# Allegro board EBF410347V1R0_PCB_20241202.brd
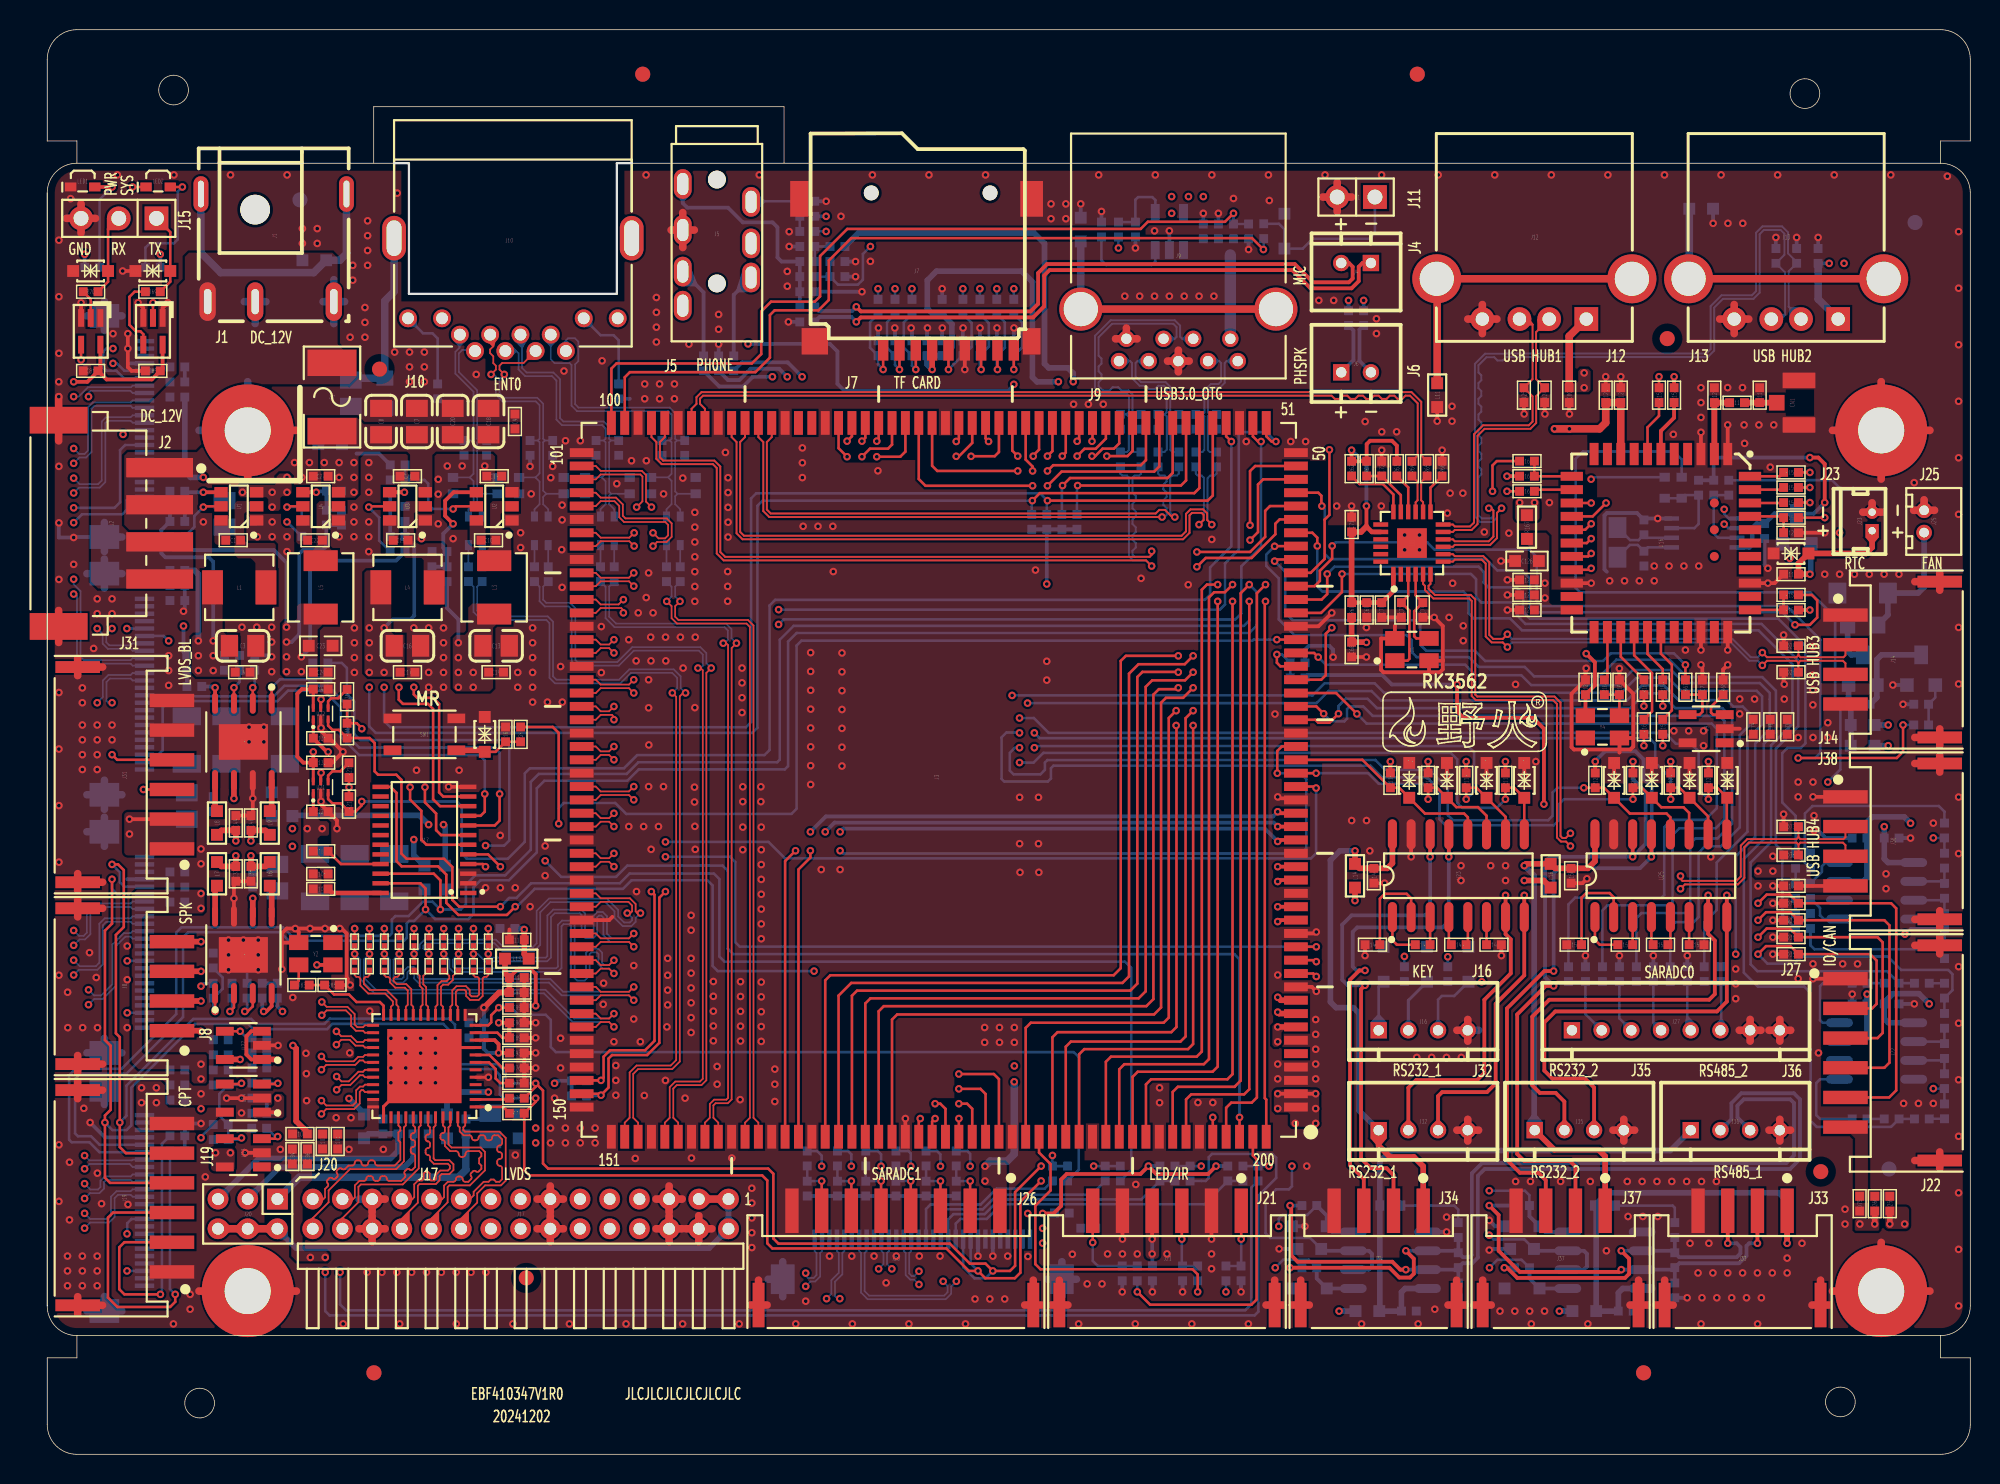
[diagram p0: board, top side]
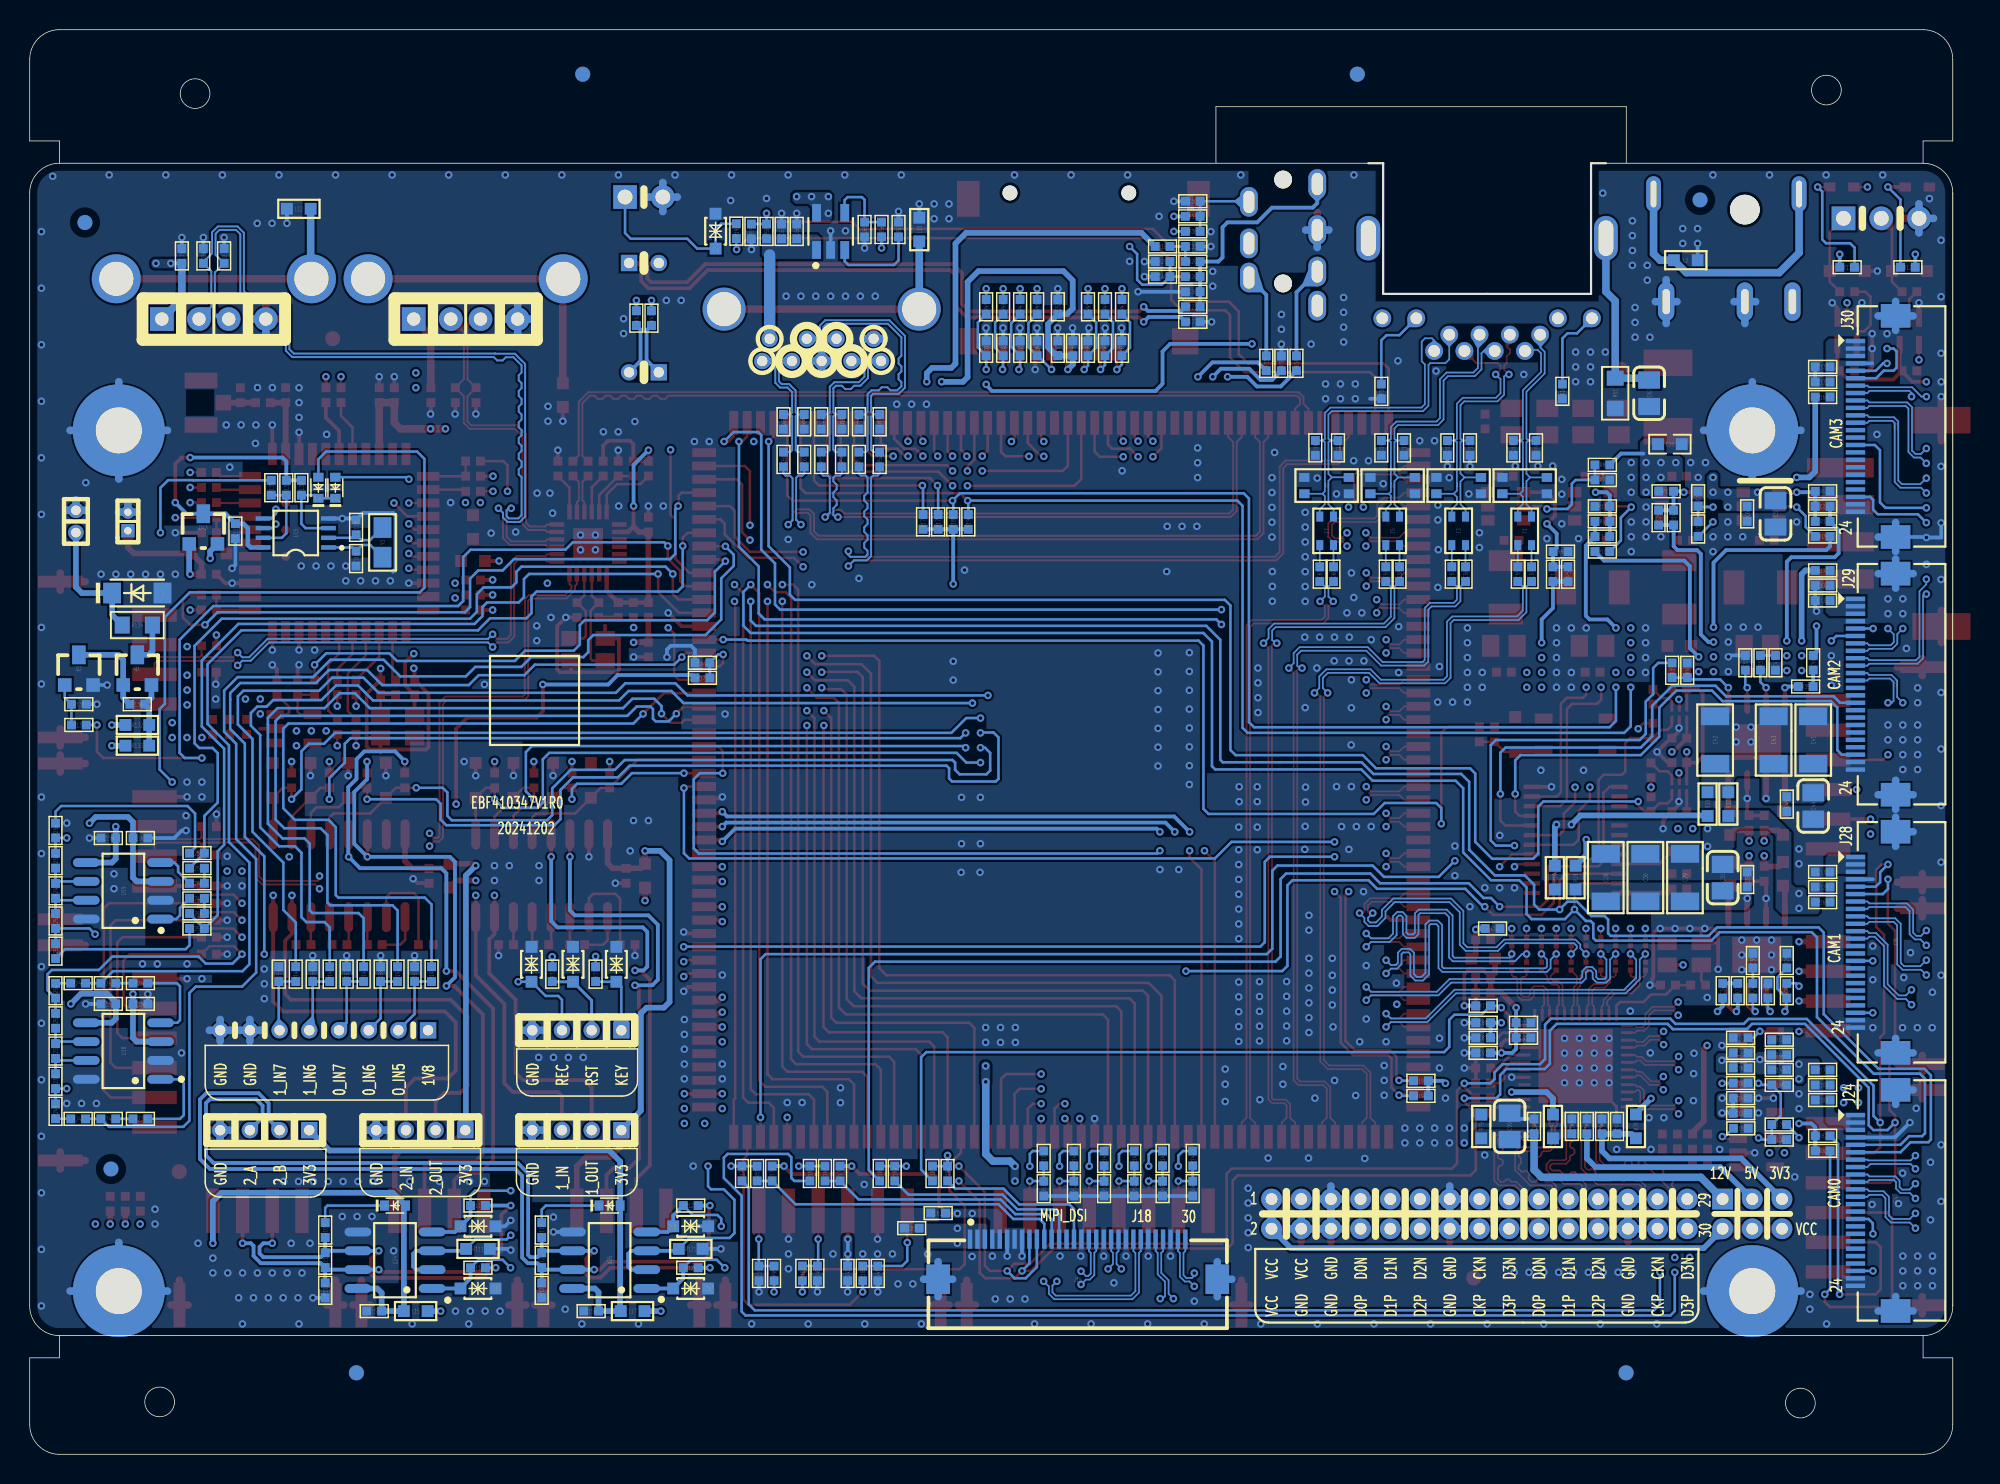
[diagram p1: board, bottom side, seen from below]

Outline 129.5 x 96 mm; copper layers: TOP, GND02, ART03, ART04, PWR05, BOTTOM. Coordinates in mm from the lower left corner of the outline.
Outline path: circle c8.51,91.93 r1 ; circle c10.26,3.45 r1 ; circle c118.36,91.69 r1 ; circle c120.75,3.53 r1 ; 0,85 0,10 ; 0,85 arc(0.59,86.41) 2,87 ; 0,85 0,10 ; 0,10 arc(0.59,8.59) 2,8 ; 2,87 2,88.5 0,88.5 0,94 arc(0.59,95.41) 2,96 127.5,96 arc(128.91,95.41) 129.5,94 129.5,88.5 127.5,88.5 127.5,87 ; 2,87 24.36,87 24.36,78.2 ; 2,8 2,6.5 0,6.5 0,2 arc(0.59,0.59) 2,0 127.5,0 arc(128.91,0.59) 129.5,2 129.5,6.5 127.5,6.5 127.5,8 ; 2,8 127.5,8 ; 21.99,87 21.99,90.81 49.62,90.81 49.62,87 ; 24.36,78.2 38.36,78.2 ; 24.36,78.2 38.36,78.2 ; 38.36,78.2 38.36,87 ; 38.36,78.2 38.36,87 ; 38.36,87 127.5,87 ; 127.5,87 arc(128.91,86.41) 129.5,85 129.5,10 arc(128.91,8.59) 127.5,8

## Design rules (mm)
net group BT_HOST_WAKE: nets BT_HOST_WAKE N16832727
net group BT_REG_ON: nets BT_REG_ON N16833114
net group BT_UART_CTS: nets BT_UART_CTS UART1_RTSN_M0
net group BT_UART_RTS: nets BT_UART_RTS UART1_CTSN_M0
net group BT_UART_RXD: nets BT_UART_RXD UART1_TX_M0
net group BT_UART_TXD: nets BT_UART_TXD UART1_RX_M0
net group BT_WAKE: nets BT_WAKE N16832725
net group CLK_32K_IN: nets CLK_32K_IN N16853193
net group DGB_RX: nets DGB_RX UART0_RX
net group DGB_TX: nets DGB_TX UART0_TX
net group EXT_PWR_EN: nets EXT_PWR_EN N16786732
net group FAN_CTRL: nets FAN_CTRL N16853902
net group HP_PLUG_IN_DET: nets HP_PLUG_IN_DET N16784225
net group I2S2_LRCK_M0: nets I2S2_LRCK_M0 PCM_SYNC
net group I2S2_SCLK_M0: nets I2S2_SCLK_M0 PCM_CLK
net group I2S2_SDI_M0: nets I2S2_SDI_M0 PCM_OUT
net group I2S2_SDO_M0: nets I2S2_SDO_M0 PCM_DIN
net group LCD_BL_PWM: nets LCD_BL_PWM MIPI_BL_PWM
net group LCD_CPT_INT: nets LCD_CPT_INT MIPI_CTP_INT
net group LCD_CPT_RST: nets LCD_CPT_RST MIPI_CTP_RST
net group LCD_RST: nets LCD_RST MIPI_LCD_RST
net group LED_BLUE: nets LED_BLUE N16990719
net group LED_RED: nets LED_RED N16990717
net group MIPI_LCD_PWR_EN: nets MIPI_LCD_PWR_EN N17004192
net group N16722097: nets N16722097 N16722109
net group N16722987: nets N16722987 N16723079
net group N16724119: nets N16724119 N16724131
net group N16783769: nets N16783769 N16783785
net group N16784039: nets N16784039 N16784053
net group N16832694: nets N16832694 N16832701
net group N16833042: nets N16833042 N16833048
net group N16853946: nets N16853946 N16854018
net group N16869660: nets N16869660 N16869662
net group N16869664: nets N16869664 N16869666
net group N16870438: nets N16870438 N16870440
net group N16870442: nets N16870442 N16870444
net group ON/OFF_KEY: nets N16816849 ON/OFF_KEY
net group PWM3_IR: nets N16990803 PWM3_IR
net group RESET_KEY: nets N16816847 RESET_KEY
net group SARADC0_IN5: nets N16827764 SARADC0_IN5
net group SARADC0_IN6: nets N16827766 SARADC0_IN6
net group SARADC0_IN7: nets N16827768 SARADC0_IN7
net group SARADC1_IN0: nets N16825657 SARADC1_IN0
net group SARADC1_IN1: nets N16825664 SARADC1_IN1
net group SARADC1_IN2: nets N16825671 SARADC1_IN2
net group SARADC1_IN3: nets N16825678 SARADC1_IN3
net group SARADC1_IN4: nets N16825685 SARADC1_IN4
net group SARADC1_IN5: nets N16825692 SARADC1_IN5
net group SARADC1_IN6: nets N16827770 SARADC1_IN6
net group SARADC1_IN7: nets N16827772 SARADC1_IN7
net group SPKN_OUT: nets N16783233 SPKN_OUT
net group SPKP_OUT: nets N16783231 SPKP_OUT
net group USB20_HOST1_DM: nets N16803237 USB20_HOST1_DM
net group USB20_HOST1_DP: nets N16803235 USB20_HOST1_DP
net group USB20_HUB_PWR_EN: nets N16810803 USB20_HUB_PWR_EN
net group USB30_DM: nets USB30_DM USB30_OTG0_DM
net group USB30_DP: nets USB30_DP USB30_OTG0_DP
net group USB30_OTG0_SSRXN: nets USB30_OTG0_SSRXN USB30_RXN
net group USB30_OTG0_SSRXP: nets USB30_OTG0_SSRXP USB30_RXP
net group USB30_OTG0_SSTXN: nets USB30_OTG0_SSTXN USB30_TXN
net group USB30_OTG0_SSTXP: nets USB30_OTG0_SSTXP USB30_TXP
net group USB30_OTG0_VBUSDET: nets USB30_OTG0_VBUSDET USB30_OTG_VBUS
net group USB30_OTG_PWR_EN: nets N16801211 USB30_OTG_PWR_EN
net group USB_HUB_D1: nets USB_HUB_DM1 USB_HUB_DP1
net group USB_HUB_D2: nets USB_HUB_DM2 USB_HUB_DP2
net group USB_HUB_D3: nets USB_HUB_DM3 USB_HUB_DP3
net group USB_HUB_D4: nets USB_HUB_DM4 USB_HUB_DP4
net group WL_HOST_WAKE: nets N16832856 WL_HOST_WAKE
net group WL_REG_ON: nets N16832815 WL_REG_ON
net group 12V: nets 12V LVDS_12V N16722243 N16783279 N16783471
net group 50OHM: nets SDMMC0_CLK SDMMC0_CMD SDMMC0_D0 SDMMC0_D1 SDMMC0_D2 SDMMC0_D3 SDMMC0_DETN SDMMC1_CLK SDMMC1_CMD SDMMC1_D0 SDMMC1_D1 SDMMC1_D2 SDMMC1_D3
net group ETH_PHY_MDIN0: nets ETH_PHY_MDIN0 MDIN0_RJ45 N16788414
net group ETH_PHY_MDIN1: nets ETH_PHY_MDIN1 MDIN1_RJ45 N16788475
net group ETH_PHY_MDIN2: nets ETH_PHY_MDIN2 MDIN2_RJ45 N16788526
net group ETH_PHY_MDIN3: nets ETH_PHY_MDIN3 MDIN3_RJ45 N16788587
net group ETH_PHY_MDIP0: nets ETH_PHY_MDIP0 MDIP0_RJ45 N16788412
net group ETH_PHY_MDIP1: nets ETH_PHY_MDIP1 MDIP1_RJ45 N16788463
net group ETH_PHY_MDIP2: nets ETH_PHY_MDIP2 MDIP2_RJ45 N16788524
net group ETH_PHY_MDIP3: nets ETH_PHY_MDIP3 MDIP3_RJ45 N16788585
net group GM8775C_DA0N: nets GM8775C_DA0N MIPI_DSI_D0N MIPI_DSI_TX_D0N
net group GM8775C_DA0P: nets GM8775C_DA0P MIPI_DSI_D0P MIPI_DSI_TX_D0P
net group GM8775C_DA1N: nets GM8775C_DA1N MIPI_DSI_D1N MIPI_DSI_TX_D1N
net group GM8775C_DA1P: nets GM8775C_DA1P MIPI_DSI_D1P MIPI_DSI_TX_D1P
net group GM8775C_DA2N: nets GM8775C_DA2N MIPI_DSI_D2N MIPI_DSI_TX_D2N
net group GM8775C_DA2P: nets GM8775C_DA2P MIPI_DSI_D2P MIPI_DSI_TX_D2P
net group GM8775C_DA3N: nets GM8775C_DA3N MIPI_DSI_D3N MIPI_DSI_TX_D3N
net group GM8775C_DA3P: nets GM8775C_DA3P MIPI_DSI_D3P MIPI_DSI_TX_D3P
net group GM8775C_DACN: nets GM8775C_DACN MIPI_DSI_CLKN MIPI_DSI_TX_CLKN
net group GM8775C_DACP: nets GM8775C_DACP MIPI_DSI_CLKP MIPI_DSI_TX_CLKP
net group GM8775C_RSTN: nets GM8775C_RSTN
net group HP_BUTTON_DET: nets HP_BUTTON_DET MIC1_INP N16784316 N16784333
net group HPL_OUT: nets HPL_OUT N16783744 N16783771 N16784431
net group HPR_OUT: nets HPR_OUT N16784027 N16784051 N16784429
net group LVDS_5V: nets LVDS_5V N16723587 N16723611 N16723631 N16853900 N16853981 VDD_CAM0_5V VDD_CAM1_5V VDD_CAM2_5V VDD_CAM3_5V
net group PWR: nets LVDS_3V3 N17000237 RS232_1_3V3 RS232_2_3V3 RS485_1_3V3 RS485_2_3V3 VCC_LVDS VCC_RTC
net group RS485_1_A: nets N16870097 RS485_1_A RS485_1_B
net group RS485_2_A: nets N16869989 RS485_2_A RS485_2_B
net group SDMMC0_CLK: nets N16783125
net group SDMMC0_CMD: nets N16783127
net group SDMMC0_D0: nets N16783123
net group SDMMC0_D1: nets N16783131
net group SDMMC0_D2: nets N16783121
net group SDMMC0_D3: nets N16783129
net group SDMMC0_DETN: nets N16783147
net group SPK_CTRL: nets N16783658 N16783940 SPK_CTRL
net group USB_HUB_3V3: nets N16803549 N16803553 N16803559 USB_HUB_3V3

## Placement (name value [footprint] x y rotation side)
C1  0.1uF  [C0402]  12.52 61.59 0 top
C2  NC  [C0402]  8.76 63.88 180 bottom
C3  22uF  [C0805]  13.16 54.48 0 top
C4  0.1uF  [C0402]  13.16 52.7 0 top
C5  22uF  [C0805]  11.94 63.37 270 bottom
C6  0.1uF  [C0402]  13.84 63.37 270 bottom
C7  22uF  [C0805]  24.89 69.59 90 top
C8  22uF  [C0805]  22.48 69.59 90 top
C9  0.1uF  [C0402]  31.5 69.59 90 top
C10  0.1uF  [C0402]  29.72 61.59 0 top
C11  0.1uF  [C0402]  23.8 61.59 0 top
C12  NC  [C0402]  26.92 59.31 270 bottom
C13  22uF  [C0805]  30.23 54.48 0 top
C14  0.1uF  [C0402]  30.23 52.7 0 top
C15  NC  [C0402]  23.6 61.85 0 bottom
C16  22uF  [C0805]  24.26 54.48 0 top
C17  0.1uF  [C0402]  24.26 52.7 0 top
C18  22uF  [C0805]  29.72 69.59 90 top
C19  0.1uF  [C0402]  30.1 65.91 180 top
C20  22uF  [C0805]  27.3 69.59 90 top
C21  0.1uF  [C0402]  24.26 65.91 180 top
C22  0.1uF  [C0402]  18.03 61.59 0 top
C23  22uF  [C0603]  18.41 54.48 0 top
C24  0.1uF  [C0402]  18.41 52.7 0 top
C25  NC  [C0402]  19.81 63.12 270 bottom
C26  22uF  [C0603]  19.05 68.07 180 bottom
C27  0.1uF  [C0402]  18.41 65.91 180 top
C28  47uF  [C1206]  23.37 38.86 90 bottom
C29  47uF  [C1206]  18.03 38.86 90 bottom
C30  47uF  [C1206]  20.7 38.86 90 bottom
C31  22uF  [C0805]  15.49 38.86 90 bottom
C32  0.1uF  [C0402]  13.84 38.73 90 bottom
C33  10uF  [C0402]  51.18 81.39 180 bottom
C34  0.1uF  [C0402]  15.49 31.24 90 bottom
C35  0.1uF  [C0402]  13.46 33.27 270 bottom
C36  270pF  [C0402]  51.18 78.34 0 bottom
C37  1nF  [C0402]  12.7 39.11 270 top
C38  1nF  [C0402]  13.72 39.11 270 top
C39  1uF  [C0402]  12.45 31.24 90 bottom
C40  0.1uF  [C0402]  53.21 79.36 0 bottom
C41  47uF  [C1206]  9.4 48.13 90 bottom
C42  47uF  [C1206]  16 48.13 90 bottom
C43  47uF  [C1206]  12.06 48.13 90 bottom
C44  22uF  [C0805]  9.4 43.69 270 bottom
C45  0.1uF  [C0402]  11.18 43.81 270 bottom
C46  0.1uF  [C0402]  9.4 53.34 270 bottom
C47  0.1uF  [C0402]  11.94 53.34 90 bottom
C48  1nF  [C0402]  13.72 42.54 90 top
C49  1nF  [C0402]  12.7 42.54 90 top
C50  0.1uF  [C0402]  51.18 84.44 0 bottom
C51  1uF  [C0402]  13.97 53.34 90 bottom
C52  10uF  [C0402]  60.26 77.33 90 bottom
C53  0.1uF  [C0402]  60.26 74.53 90 bottom
C54  0.1uF  [C0402]  28.37 59.31 90 bottom
C55  0.1uF  [C0402]  29.29 59.31 90 bottom
C56  0.1uF  [C0402]  32.81 59.31 90 bottom
C57  0.1uF  [C0402]  33.74 59.31 90 bottom
C58  0.1uF  [C0402]  37.26 59.31 90 bottom
C59  0.1uF  [C0402]  38.18 59.31 90 bottom
C60  0.1uF  [C0402]  41.7 59.31 90 bottom
C61  0.1uF  [C0402]  42.63 59.31 90 bottom
C62  1nF  [C0805]  20.45 71.5 90 bottom
C63  0.1uF  [C0402]  77.34 67.04 270 bottom
C64  0.1uF  [C0402]  78.74 67.04 270 bottom
C65  0.1uF  [C0402]  73.28 82.53 270 bottom
C66  10uF  [C0402]  77.85 82.41 90 bottom
C67  0.1uF  [C0402]  78.87 82.41 90 bottom
C68  0.1uF  [C0402]  87.84 54.23 270 top
C69  4.7uF  [C0402]  88.85 56.89 270 top
C70  0.1uF  [C0402]  89.87 56.89 270 top
C71  0.1uF  [C0402]  87.84 62.66 90 top
C72  0.1uF  [C0402]  89.87 66.42 90 top
C73  NC  [C0402]  91.19 56.89 270 top
C74  NC  [C0402]  92.64 56.89 270 top
C75  0.1uF  [C0402]  119.25 80.75 90 bottom
C76  0.1uF  [C0402]  117.17 49.02 90 top
C77  0.1uF  [C0402]  111.46 51.69 90 top
C78  10uF  [C0402]  116.03 49.02 90 top
C79  0.1uF  [C0402]  114.89 49.02 90 top
C80  0.1uF  [C0402]  102.49 71.37 270 top
C81  0.1uF  [C0402]  2.92 73.01 180 top
C82  0.1uF  [C0402]  68.33 16.25 0 bottom
C83  10uF  [C0402]  70.1 15.24 0 bottom
C84  10uF  [C0402]  16.51 20.06 90 top
C85  0.1uF  [C0402]  7.11 73.01 180 top
C86  0.1uF  [C0402]  17.53 20.06 90 top
C87  10nF  [C0402]  31.62 28.07 0 bottom
C88  10nF  [C0402]  31.62 29.08 0 bottom
C89  1uF  [C0402]  31.62 28.07 0 top
C90  1uF  [C0402]  31.62 29.08 0 top
C91  10nF  [C0402]  28.91 28.07 180 bottom
C92  0.1uF  [C0402]  31.62 27.05 0 bottom
C93  10nF  [C0402]  31.62 27.05 0 top
C94  0.1uF  [C0402]  31.62 31.11 0 top
C95  0.22uF  [C0402]  31.62 30.1 0 top
C96  0.1uF  [C0402]  23.62 22.1 90 bottom
C97  10uF  [C0402]  22.61 22.1 90 bottom
C98  0.1uF  [C0402]  28.19 22.1 90 bottom
C99  22uF  [C0805]  29.84 22.1 90 bottom
C100  10nF  [C0402]  17.02 21.59 180 top
C101  0.1uF  [C0402]  19.56 21.08 270 top
C102  10nF  [C0402]  11.68 27.94 180 bottom
C103  0.1uF  [C0402]  18.54 21.08 270 top
C104  0.1uF  [C0402]  24.64 22.1 90 bottom
C105  10uF  [C0402]  25.65 22.1 90 bottom
C106  10uF  [C0402]  18.41 39.11 180 top
C107  0.1uF  [C0402]  18.41 38.1 180 top
C108  10uF  [C0402]  8.76 24.89 0 bottom
C109  0.1uF  [C0402]  8.76 23.87 0 bottom
C110  10uF  [C0402]  30.99 35.43 180 bottom
C111  0.1uF  [C0402]  31.62 34.67 180 top
C112  0.1uF  [C0402]  28.91 29.08 180 bottom
C113  10uF  [C0402]  31.62 32.13 0 top
C114  10pF  [C0402]  113.79 70.86 180 top
C115  NC  [C0402]  115.32 71.37 90 top
C116  10uF  [C0402]  117.43 59.31 180 top
C117  0.1uF  [C0402]  115.65 62.21 270 bottom
C118  18pF  [C0402]  107.52 60.36 270 bottom
C119  18pF  [C0402]  107.52 62.47 90 bottom
C120  NC  [C0402]  112.26 71.37 90 top
C121  10uF  [C0402]  104.95 71.37 90 top
C122  0.1uF  [C0402]  105.96 71.37 90 top
C123  0.1uF  [C0402]  103.58 51.69 90 top
C124  0.1uF  [C0402]  99.65 56.89 180 top
C125  10uF  [C0402]  99.65 57.91 180 top
C126  22uF  [C0603]  99.65 60.2 180 top
C127  0.1uF  [C0402]  99.65 58.93 180 top
C128  0.1uF  [C0402]  18.41 43.31 0 top
C129  10uF  [C0402]  8.76 38.23 0 bottom
C130  0.1uF  [C0402]  8.76 39.24 0 bottom
C131  10uF  [C0402]  8.76 72.26 0 bottom
C132  0.1uF  [C0402]  18.41 46.61 0 top
C133  0.1uF  [C0402]  8.76 73.28 0 bottom
C134  10uF  [C0402]  8.76 58.55 0 bottom
C135  0.1uF  [C0402]  8.76 57.53 0 bottom
C136  0.1uF  [C0402]  18.41 48.26 0 top
C137  0.1uF  [C0402]  117.43 38.3 180 top
C138  0.1uF  [C0402]  11.68 21.21 180 bottom
C139  10uF  [C0402]  14.29 22.99 180 bottom
C140  0.1uF  [C0402]  14.29 24 180 bottom
C141  0.1uF  [C0402]  14.29 27.05 180 bottom
C142  0.1uF  [C0402]  11.68 25.91 180 bottom
C143  0.1uF  [C0402]  18.41 51.56 0 top
C144  0.1uF  [C0402]  89.33 38.99 270 top
C145  0.1uF  [C0402]  11.68 24.89 180 bottom
C146  0.1uF  [C0402]  89.24 34.34 180 top
C147  0.1uF  [C0402]  97.42 34.34 0 top
C148  0.1uF  [C0402]  92.62 34.34 180 top
C149  0.1uF  [C0402]  95.05 34.34 180 top
C150  0.1uF  [C0402]  102.62 38.99 270 top
C151  0.1uF  [C0402]  106.26 34.34 180 top
C152  0.1uF  [C0402]  108.64 34.34 180 top
C153  0.1uF  [C0402]  106.3 9.65 0 bottom
C154  0.1uF  [C0402]  102.82 34.34 180 top
C155  0.1uF  [C0402]  111.06 34.34 0 top
C156  0.1uF  [C0402]  91.69 9.65 0 bottom
C157  0.1uF  [C0402]  124.21 30.35 0 bottom
C158  0.1uF  [C0402]  122.05 30.35 180 bottom
C159  0.1uF  [C0402]  124.21 41.53 0 bottom
C160  10uF  [C0402]  14.29 26.03 180 bottom
C161  0.1uF  [C0402]  122.05 41.53 180 bottom
C162  22nF  [C0402]  14.29 28.07 0 bottom
C164  10uF  [C0402]  11.68 26.92 180 bottom
C165  NC  [C0402]  30.86 48.51 90 top
CN1  WiFi-Ant  [UFL-3]  117.97 70.86 270 top
D1  KLXES15AAA1  [ES0402]  65.09 74.53 90 bottom
D2  KLXES15AAA1  [ES0402]  63.95 74.53 90 bottom
D3  KLXES15AAA1  [ES0402]  62.8 74.53 90 bottom
D4  KLXES15AAA1  [ES0402]  61.66 74.53 90 bottom
D5  KLXES15AAA1  [ES0402]  58.23 74.53 90 bottom
D6  KLXES15AAA1  [ES0402]  57.09 74.53 90 bottom
D7  KLXES15AAA1  [ES0402]  55.95 74.53 90 bottom
D8  KLXES15AAA1  [ES0402]  59.25 74.53 90 bottom
D9  KLXES15AAA1  [ES0402]  28.07 67.82 90 bottom
D10  KLXES15AAA1  [ES0402]  29.59 67.82 90 bottom
D11  KLXES15AAA1  [ES0402]  32.51 67.82 90 bottom
D12  KLXES15AAA1  [ES0402]  34.04 67.82 90 bottom
D13  KLXES15AAA1  [ES0402]  36.96 67.82 90 bottom
D14  KLXES15AAA1  [ES0402]  38.48 67.82 90 bottom
D15  KLXES15AAA1  [ES0402]  41.4 67.82 90 bottom
D16  KLXES15AAA1  [ES0402]  42.93 67.82 90 bottom
D17  KLXES15AAA1  [ES0402]  72.26 69.58 270 bottom
D18  KLXES15AAA1  [ES0402]  73.66 69.58 270 bottom
D19  KLXES15AAA1  [ES0402]  74.8 69.58 270 bottom
D20  KLXES15AAA1  [ES0402]  76.2 69.58 270 bottom
D21  KLXES15AAA1  [ES0402]  77.34 69.58 270 bottom
D22  KLXES15AAA1  [ES0402]  78.74 69.58 270 bottom
D23  PESD3V3L1BA  [SOD323_T]  83.31 82.42 90 bottom
D24  KLXES15AAA1  [ES0402]  100.84 71.37 270 top
D25  KLXES15AAA1  [ES0402]  99.44 71.37 270 top
D26  KLXES15AAA1  [ES0402]  117.81 80.75 90 bottom
D27  KLXES15AAA1  [ES0402]  116.41 80.75 90 bottom
D28  KLXES15AAA1  [ES0402]  117.43 52.7 180 top
D29  KLXES15AAA1  [ES0402]  117.43 54.48 180 top
D30  PESD3V3L1BA  [SOD323_T]  2.92 79.74 180 top
D31  PESD3V3L1BA  [SOD323_T]  7.11 79.74 180 top
D32  PESD3V3L1BA  [SOD323_T]  89.99 33.02 90 bottom
D33  PESD3V3L1BA  [SOD323_T]  92.92 33.02 90 bottom
D34  PESD3V3L1BA  [SOD323_T]  95.71 33.02 90 bottom
D35  KLXES15AAA1  [ES0402]  117.43 33.7 180 top
D36  KLXES15AAA1  [ES0402]  117.43 34.85 180 top
D37  KLXES15AAA1  [ES0402]  117.43 35.99 180 top
D38  KLXES15AAA1  [ES0402]  117.43 40.38 180 top
D39  KLXES15AAA1  [ES0402]  80.39 12.19 270 bottom
D40  KLXES15AAA1  [ES0402]  76.45 12.19 270 bottom
D41  KLXES15AAA1  [ES0402]  72.39 12.19 270 bottom
D42  KLXES15AAA1  [ES0402]  74.42 12.19 270 bottom
D43  BAT54C  [SOT23]  117.81 62.34 180 bottom
D44  PESD3V3L1BA  [SOD323_T]  117.43 60.7 0 top
D45  RB521S-30  [SOD523]  108.92 65.13 90 bottom
D46  RB521S-30  [SOD523]  110.06 65.13 90 bottom
D47  1N4148W  [SOD-123]  122.25 58.04 0 bottom
D48  KLXES15AAA1  [ES0402]  51.18 17.91 270 bottom
D49  KLXES15AAA1  [ES0402]  53.21 17.91 270 bottom
D50  KLXES15AAA1  [ES0402]  55.12 17.91 270 bottom
D51  KLXES15AAA1  [ES0402]  57.15 17.91 270 bottom
D52  KLXES15AAA1  [ES0402]  59.18 17.91 270 bottom
D53  KLXES15AAA1  [ES0402]  61.21 17.91 270 bottom
D54  RB521S-30  [SOD523]  104.9 16.76 180 bottom
D55  KLXES15AAA1  [ES0402]  112.73 32.36 90 bottom
D56  KLXES15AAA1  [ES0402]  110.44 32.36 90 bottom
D57  KLXES15AAA1  [ES0402]  108.16 32.36 90 bottom
D58  KLXES15AAA1  [ES0402]  105.87 32.36 90 bottom
D59  KLXES15AAA1  [ES0402]  103.58 32.36 90 bottom
D60  PESD3V3L1BA  [SOD323_T]  99.31 11.17 180 bottom
D61  PESD3V3L1BA  [SOD323_T]  99.31 15.37 180 bottom
D62  PESD3V3L1BA  [SOD323_T]  99.46 45.41 90 top
D63  PESD3V3L1BA  [SOD323_T]  96.92 45.41 90 top
D64  PESD3V3L1BA  [SOD323_T]  91.72 45.41 90 top
D65  PESD3V3L1BA  [SOD323_T]  94.26 45.41 90 top
D66  RB521S-30  [SOD523]  90.45 16.76 180 bottom
D67  PESD3V3L1BA  [SOD323_T]  84.99 11.17 180 bottom
D68  PESD3V3L1BA  [SOD323_T]  84.99 15.37 180 bottom
D69  PESD3V3L1BA  [SOD323_T]  113.13 45.41 90 top
D70  PESD3V3L1BA  [SOD323_T]  110.59 45.41 90 top
D71  PESD3V3L1BA  [SOD323_T]  105.51 45.41 90 top
D72  PESD3V3L1BA  [SOD323_T]  108.05 45.41 90 top
D73  KLXES15AAA1  [ES0402]  117.43 42.29 180 top
D74  KLXES15AAA1  [ES0402]  117.43 37.13 180 top
D75  KLXES15AAA1  [ES0402]  122.05 16.89 270 top
D76  PESD3V3L1BA  [SOD323_T]  29.46 48.51 90 top
F1  SMD1812P200TF16  [F1812]  19.18 71.25 270 top
J1  DC-044A-20A  [DC_IN_TH_3P_10R1X11R6]  15.25 82.18 270 top
J2  -  [HC-XH-4AWT]  7.57 62.74 270 top
J3  RK3562-HH200  [HH200-0R90-48R1X48R1-B]  60.04 45.45 90 top
J4  PH-2A  [PH-1X2-2P0_L]  88.14 80.28 180 top
J5  PJ-393-7P  [AV7_6X14R50_TM]  45.1 82.4 0 top
J6  PH-2A  [PH-1X2-2P0_L]  88.14 72.91 0 top
J7  TF_Card  [TFCARD]  59.49 85 180 top
J8  PH-4PWBPZ  [PH2R0-A-1X4]  4.6 33.55 90 top
J9  USB30_AF  [USB9-A-16R5X14R45-TM]  76.17 77.17 180 top
J10  RC01835  [RJ8-15R2X16R2-TM-LED]  31.36 81.95 0 top
J11  -  [HDR1X2-2R54-TM-VM]  88.14 84.72 180 top
J12  USB  [USB-A-SM]  100.14 76.5 180 top
J13  USB  [USB-A-SM]  117.1 76.5 180 top
J14  PH-4PWBPZ  [PH2R0-A-1X4]  124.89 51.56 270 top
J15  -  [HDR1X3-2R54-TM-VM]  4.82 83.29 180 top
J16  PH-4A  [PH-1X4-2P0]  92.66 28.57 0 top
J17  2X15PIN-M  [HDR1X15-2-TM-RM]  31.88 16.2 180 top
J18  FPC_0R5_30P_D  [FPC-30P-0P5]  58.93 13.15 180 bottom
J19  PH-6PWBPZ  [PH2R0-A-1X6]  4.6 17.29 90 top
J20  2X3PIN-M  [HDR2X3-2R00-TM-VM]  13.5 16.2 180 top
J21  PH-6PWBPZ  [PH2R0-A-1X6]  75.4 12.61 180 top
J22  PH-6PWBPZ  [PH2R0-A-1X6]  124.89 27.05 270 top
J23  1.25T-2A  [GH1P25_TH_2P]  122.89 62.86 90 top
J24  FPC_0P5_24P_D  [FPC_24P_0P5]  5.2 17.11 270 bottom
J25  A1501WV-2P  [ZH1P5MM_TH_2P]  126.39 62.86 90 top
J26  PH-8PWBPZ  [PH2R0-A-1X8]  57.15 12.61 180 top
J27  PH-8A  [PH-1X8-2P0]  109.67 28.57 0 top
J28  FPC_0P5_24P_D  [FPC_24P_0P5]  5.2 34.5 270 bottom
J29  FPC_0P5_24P_D  [FPC_24P_0P5]  5.2 51.9 270 bottom
J30  FPC_0P5_24P_D  [FPC_24P_0P5]  5.2 69.26 270 bottom
J31  PH-6PWBPZ  [PH2R0-A-1X6]  4.6 45.8 90 top
J32  PH-4A  [PH-1X4-2P0]  92.66 21.84 0 top
J33  PH-4PWBPZ  [PH2R0-A-1X4]  112.17 12.61 180 top
J34  PH-4PWBPZ  [PH2R0-A-1X4]  87.66 12.61 180 top
J35  PH-4A  [PH-1X4-2P0]  103.17 21.84 0 top
J36  PH-4A  [PH-1X4-2P0]  113.67 21.84 0 top
J37  PH-4PWBPZ  [PH2R0-A-1X4]  99.91 12.61 180 top
J38  PH-4PWBPZ  [PH2R0-A-1X4]  124.89 39.3 270 top
L1  3.3uH  [L4520]  12.93 58.42 180 top
L2  100R 100MHz  [L0603]  17.98 80.47 180 bottom
L3  3.3uH  [L4520]  30.1 58.42 270 top
L4  3.3uH  [L4520]  24.26 58.42 180 top
L5  3.3uH  [L4520]  18.41 58.42 270 top
L6  1K 100MHz  [L0603]  14.99 39.11 90 top
L7  1K 100MHz  [L0603]  11.43 39.11 90 top
L8  1K 100MHz  [L0603]  11.43 42.54 270 top
L9  1K 100MHz  [L0603]  14.99 42.54 270 top
L10  100R 100MHz  [L0603]  69.6 82.53 270 bottom
L11  100R 100MHz  [L0603]  93.6 71.37 90 top
L12  100R 100MHz  [L0603]  111.38 83.93 180 bottom
L13  100R 100MHz  [L0603]  31.62 33.4 180 top
L14  100R 100MHz  [L0603]  88.06 38.99 270 top
L15  100R 100MHz  [L0603]  103.5 9.65 0 bottom
L16  100R 100MHz  [L0603]  101.24 38.99 270 top
L17  100R 100MHz  [L0603]  88.9 9.65 0 bottom
LED1  HS-0602-UR  [LED_HS_0602_UR]  2.39 85.4 0 top
LED2  HS-0602-UG  [LED_HS_0602_UR]  7.47 85.4 0 top
NOREF  -  [unnamed]  109.09 75.18 0 top
NOREF#2  -  [#2]  0 10 0 top
NOREF#3  -  [unnamed]  40.1 93 180 top
NOREF#4  -  [#2]  95.5 50.8 0 top
NOREF#5  -  [unnamed]  22.38 73.13 0 top
NOREF#6  -  [#2]  2 8 90 top
NOREF#7  -  [unnamed]  32.26 11.89 0 top
NOREF#8  -  [unnamed]  107.5 5.49 0 top
NOREF#9  -  [unnamed]  22 5.49 0 top
NOREF#10  -  [unnamed]  119.43 19.05 0 top
NOREF#11  -  [unnamed]  92.26 93 180 top
NOREF#12  -  [unnamed]  40.1 93 180 bottom
NOREF#13  -  [unnamed]  125.78 83.01 180 bottom
NOREF#14  -  [unnamed]  17.02 84.53 180 bottom
NOREF#15  -  [unnamed]  92.26 93 180 bottom
NOREF#16  -  [unnamed]  22 5.49 180 bottom
NOREF#17  -  [unnamed]  107.5 5.49 180 bottom
NOREF#18  -  [unnamed]  124.03 19.23 180 bottom
Q1  SSM3J328R-LF  [SOT23]  122.25 52.83 180 bottom
Q2  SS8050  [SOT23]  126.19 52.83 180 bottom
R1  115K  [R0402]  8.76 62.86 180 bottom
R2  10K  [R0402]  17.14 64.39 90 bottom
R3  1K  [R0402]  17.14 62.36 270 bottom
R4  20K  [R0402]  8.76 64.9 180 bottom
R5  115K  [R0402]  25.91 59.31 270 bottom
R6  115K  [R0402]  23.6 62.86 0 bottom
R7  27K  [R0402]  23.6 65.66 180 bottom
R8  180K  [R0402]  23.6 66.67 180 bottom
R9  20K  [R0402]  26.42 60.83 180 bottom
R10  1K  [R0402]  23.6 60.83 0 bottom
R11  20K  [R0402]  23.6 63.88 0 bottom
R12  5.1K  [R0402]  3.02 79.99 0 bottom
R13  4.7K  [R0402]  7.11 79.99 180 bottom
R14  100K  [R0402]  18.8 63.12 270 bottom
R15  1K  [R0402]  8.76 61.85 180 bottom
R16  510R  [R0402]  26.29 71.63 270 bottom
R17  30K  [R0402]  19.3 64.9 0 bottom
R18  100R  [R0402]  53.21 81.39 0 bottom
R19  0R  [R0603]  26.8 38.86 270 bottom
R20  2.2K  [R0402]  51.18 80.37 180 bottom
R21  NC  [R0603]  25.4 38.86 270 bottom
R22  20K  [R0402]  14.48 31.24 270 bottom
R23  0R  [R0402]  51.18 77.33 0 bottom
R24  20K  [R0402]  13.46 31.24 270 bottom
R25  1K  [R0402]  11.18 31.24 270 bottom
R26  100K  [R0402]  51.18 79.36 0 bottom
R27  0R  [R0402]  51.18 76.31 0 bottom
R28  10K  [R0402]  11.18 33.27 90 bottom
R29  100K  [R0402]  53.21 80.37 0 bottom
R30  0R  [R0603]  16.51 43.81 90 bottom
R31  100K  [R0402]  51.18 83.42 0 bottom
R32  NC  [R0603]  15.11 43.81 90 bottom
R33  0R  [R0402]  46.23 73.52 270 bottom
R34  0R  [R0402]  44.2 73.52 270 bottom
R35  20K  [R0402]  9.91 51.74 0 bottom
R36  0R  [R0402]  51.18 82.41 0 bottom
R37  20K  [R0402]  12.95 53.34 270 bottom
R38  0R  [R0402]  45.21 73.52 270 bottom
R39  1K  [R0402]  18.9 52.83 270 bottom
R40  10K  [R0402]  17.88 52.83 90 bottom
R41  0R  [R0402]  87.63 76.56 270 bottom
R42  0R  [R0402]  88.65 76.56 270 bottom
R43  22R  [R0402]  55.95 77.33 270 bottom
R44  22R  [R0402]  57.09 77.33 270 bottom
R45  22R  [R0402]  58.23 77.33 270 bottom
R46  22R  [R0402]  61.66 77.33 270 bottom
R47  22R  [R0402]  62.8 77.33 270 bottom
R48  22R  [R0402]  63.95 77.33 270 bottom
R49  0R  [R0402]  65.09 77.33 270 bottom
R50  510R  [R0402]  38.48 71.63 270 bottom
R51  1M  [R0805]  22.73 71.5 90 bottom
R52  2.2R  [R0402]  72.26 67.04 270 bottom
R53  2.2R  [R0402]  73.66 67.04 270 bottom
R54  0R  [R0402]  74.8 67.04 270 bottom
R55  0R  [R0402]  76.2 67.04 270 bottom
R56  1K  [R0402]  72.14 82.53 90 bottom
R57  3.4K  [R0402]  70.99 82.53 90 bottom
R58  10K  [R0402]  79.88 82.41 90 bottom
R59  15K  [R0402]  80.9 82.41 270 bottom
R60  0R  [R0402]  87.84 56.89 90 top
R61  100K  [R0402]  88.85 66.42 90 top
R62  100K  [R0402]  87.84 66.42 90 top
R63  100K  [R0402]  90.88 66.42 90 top
R64  2.2R  [R0402]  91.9 66.42 90 top
R65  2.2R  [R0402]  92.92 66.42 90 top
R66  2.7K  [R0402]  93.93 66.42 90 top
R67  1K  [R0402]  110.31 51.69 270 top
R68  3.4K  [R0402]  112.85 51.69 90 top
R69  100R  [R0402]  7.11 78.34 180 top
R70  100R  [R0402]  2.92 78.34 180 top
R71  100R  [R0402]  91.39 32.36 90 bottom
R72  100R  [R0402]  94.31 32.36 90 bottom
R73  4.7K  [R0402]  31.62 30.22 180 bottom
R74  NC  [R0402]  31.62 22.99 180 top
R75  NC  [R0402]  31.62 24 180 top
R76  10K  [R0402]  31.62 26.03 180 top
R77  10K  [R0402]  31.62 25.02 180 top
R78  0R  [R0603]  21.34 22.1 270 bottom
R79  0R  [R0603]  31.75 22.1 270 bottom
R80  10K  [R0402]  8.76 20.45 180 bottom
R81  NC  [R0402]  80.52 18.92 270 bottom
R82  10K  [R0402]  8.76 21.46 180 bottom
R83  NC  [R0402]  17.14 31.62 0 top
R84  0R  [R0603]  26.92 22.1 270 bottom
R85  0R  [R0402]  19.18 31.62 0 top
R86  0R  [R0201]  29.7 32.89 270 top
R87  NC  [R0201]  29.7 34.54 90 top
R88  NC  [R0201]  28.7 34.54 90 top
R89  0R  [R0201]  28.7 32.89 270 top
R90  0R  [R0201]  27.7 32.89 270 top
R91  NC  [R0201]  27.7 34.54 90 top
R92  NC  [R0201]  26.7 34.54 90 top
R93  0R  [R0201]  26.7 32.89 270 top
R94  0R  [R0201]  23.7 32.89 270 top
R95  NC  [R0201]  23.7 34.54 90 top
R96  NC  [R0201]  22.7 34.54 90 top
R97  0R  [R0201]  22.7 32.89 270 top
R98  100R  [R0402]  79.38 12.19 90 bottom
R99  0R  [R0201]  21.7 32.89 270 top
R100  NC  [R0201]  21.7 34.54 90 top
R101  NC  [R0201]  20.7 34.54 90 top
R102  0R  [R0201]  20.7 32.89 270 top
R103  100R  [R0402]  77.47 12.19 90 bottom
R104  0R  [R0201]  25.7 32.89 270 top
R105  NC  [R0201]  25.7 34.54 90 top
R106  NC  [R0201]  24.7 34.54 90 top
R107  0R  [R0201]  24.7 32.89 270 top
R108  100R  [R0402]  73.41 12.19 90 bottom
R109  4.7K  [R0402]  109.6 15.11 90 bottom
R110  120R  [R0402]  109.6 13.08 90 bottom
R111  10K  [R0603]  99.31 13.84 180 bottom
R112  4.7K  [R0402]  109.6 11.05 270 bottom
R113  NC  [R0402]  98.19 45.41 90 top
R114  NC  [R0402]  95.55 45.41 90 top
R115  NC  [R0402]  99.31 12.57 180 bottom
R116  NC  [R0402]  90.45 45.41 90 top
R117  NC  [R0402]  99.31 16.76 180 bottom
R118  NC  [R0402]  92.99 45.41 90 top
R119  4.7K  [R0402]  95.02 15.11 90 bottom
R120  120R  [R0402]  95.02 13.08 90 bottom
R121  10K  [R0603]  84.99 13.84 180 bottom
R122  4.7K  [R0402]  95.02 11.05 270 bottom
R123  NC  [R0402]  111.86 45.41 90 top
R124  NC  [R0402]  109.32 45.41 90 top
R125  NC  [R0402]  84.99 12.57 180 bottom
R126  NC  [R0402]  104.24 45.41 90 top
R127  NC  [R0402]  84.99 16.76 180 bottom
R128  NC  [R0402]  106.78 45.41 90 top
R129  NC  [R0402]  117.43 62.1 0 top
R130  10K  [R0402]  111.2 65.13 270 bottom
R131  10K  [R0402]  112.22 65.13 270 bottom
R132  0R  [R0603]  122.25 49.15 180 bottom
R133  NC  [R0603]  122.25 47.75 180 bottom
R134  10R  [R0805]  122.25 55.88 0 bottom
R135  22R  [R0402]  113.24 65.13 90 bottom
R136  10K  [R0402]  122.25 50.54 0 bottom
R137  1K  [R0402]  126.19 49.15 0 bottom
R138  10K  [R0402]  126.19 50.54 180 bottom
R139  100R  [R0402]  61.21 19.94 90 bottom
R140  100R  [R0402]  59.18 19.94 90 bottom
R141  100R  [R0402]  57.15 19.94 90 bottom
R142  100R  [R0402]  55.12 19.94 90 bottom
R143  100R  [R0402]  53.21 19.94 90 bottom
R144  100R  [R0402]  51.18 19.94 90 bottom
R145  100R  [R0402]  102.44 32.36 90 bottom
R146  100R  [R0402]  104.73 32.36 90 bottom
R147  100R  [R0402]  107.01 32.36 90 bottom
R148  100R  [R0402]  109.3 32.36 90 bottom
R149  100R  [R0402]  111.58 32.36 90 bottom
R150  0R  [R0402]  117.43 63.12 180 top
R151  10K  [R0402]  117.43 56.89 180 top
R152  0R  [R0402]  117.43 64.13 180 top
R153  0R  [R0402]  117.43 65.15 180 top
R154  0R  [R0402]  117.43 66.17 180 top
R155  0R  [R0402]  117.43 57.91 0 top
R156  0R  [R0402]  109.55 71.37 270 top
R157  22R  [R0402]  108.79 49.02 270 top
R158  0R  [R0402]  108.54 71.37 270 top
R159  22R  [R0402]  108.79 51.69 270 top
R160  22R  [R0402]  107.52 49.02 270 top
R161  22R  [R0402]  107.52 51.69 270 top
R162  22R  [R0402]  104.85 51.69 270 top
R163  NC  [R0402]  105.87 51.69 90 top
R164  10K  [R0402]  99.65 65.91 0 top
R165  0R  [R0402]  99.65 66.93 0 top
R166  0R  [R0402]  99.65 64.9 0 top
R167  0R  [R0603]  99.65 62.48 270 top
R168  0R  [R0402]  8.76 37.21 180 bottom
R169  0R  [R0402]  8.76 71.25 180 bottom
R170  0R  [R0402]  8.76 59.56 180 bottom
R171  49.9K  [R0402]  84.2 52.32 180 bottom
R172  0R  [R0402]  8.76 25.91 180 bottom
R173  10K  [R0402]  84.2 53.34 0 bottom
R174  2.2K  [R0402]  69.34 62.83 90 bottom
R175  2.2K  [R0402]  68.33 62.83 90 bottom
R176  NC  [R0402]  79.5 18.92 270 bottom
R177  NC  [R0402]  74.93 18.92 270 bottom
R178  0R  [R0402]  81.53 18.92 270 bottom
R179  1K  [R0402]  11.68 22.22 0 bottom
R180  3.4K  [R0402]  14.27 21.97 180 bottom
R181  3.4K  [R0402]  14.29 25.02 180 bottom
R182  NC  [R0402]  75.95 18.92 270 bottom
R183  0R  [R0402]  76.96 18.92 270 bottom
R184  NC  [R0402]  71.25 18.92 270 bottom
R185  0R  [R0402]  72.26 18.92 270 bottom
R186  NC  [R0402]  67.69 18.92 270 bottom
R187  0R  [R0402]  68.71 18.92 270 bottom
R188  10K  [R0402]  18.41 40.64 0 top
R189  2.2K  [R0402]  67.31 62.83 90 bottom
R190  2.2K  [R0402]  66.29 62.83 90 bottom
R191  2.2K  [R0402]  35.81 25.17 0 bottom
R192  2.2K  [R0402]  35.81 24.15 0 bottom
R193  100R  [R0402]  81.92 82.42 270 bottom
R213  NC  [R0402]  20.32 43.81 90 top
R214  NC  [R0402]  20.19 48.77 90 top
R215  10K  [R0402]  20.32 46.1 270 top
R216  10K  [R0402]  20.19 51.05 270 top
R237  120R  [R0402]  127.76 27.18 90 bottom
R238  NC  [R0402]  127.76 25.14 270 bottom
R239  22R  [R0402]  122.05 22.6 180 bottom
R240  22R  [R0402]  122.05 31.75 180 bottom
R241  NC  [R0402]  124.21 22.6 180 bottom
R242  0R  [R0402]  126.24 22.6 0 bottom
R243  NC  [R0402]  124.21 31.75 180 bottom
R244  0R  [R0402]  126.24 31.75 0 bottom
R245  22R  [R0402]  118.24 37.46 0 bottom
R246  22R  [R0402]  118.24 38.48 0 bottom
R247  120R  [R0402]  127.76 37.97 90 bottom
R248  NC  [R0402]  118.24 36.45 180 bottom
R249  0R  [R0402]  127.76 23.11 90 bottom
R250  0R  [R0402]  127.76 31.24 270 bottom
R251  NC  [R0402]  127.76 29.21 90 bottom
R252  NC  [R0402]  127.76 35.94 270 bottom
R253  0R  [R0402]  118.24 35.43 0 bottom
R254  0R  [R0402]  127.76 33.91 90 bottom
R255  0R  [R0402]  118.24 40.51 0 bottom
R256  0R  [R0402]  127.76 42.04 270 bottom
R257  NC  [R0402]  118.24 39.5 180 bottom
R258  NC  [R0402]  127.76 40 90 bottom
R259  NC  [R0402]  124.08 16.89 90 top
R260  0R  [R0402]  123.06 16.89 90 top
R261  22R  [R0402]  31.88 48.51 270 top
SS1  -  [PTH_M3]  13.5 11 0 top
SS2  -  [PTH_M3]  123.5 11 0 top
SS3  -  [PTH_M3]  123.5 69 0 top
SS4  -  [PTH_M3]  13.5 69 0 top
SW1  SW_PB_ESW  [SW4-4R20X3R25-SM]  25.4 48.51 180 top
T1  WBA0805D801PT-HF  [L4_2012_T]  28.83 62.23 90 bottom
T2  WBA3416L600T-D-HF  [L4_3216_T]  28.83 65.28 0 bottom
T3  WBA0805D801PT-HF  [L4_2012_T]  33.27 62.23 90 bottom
T4  WBA3416L600T-D-HF  [L4_3216_T]  33.27 65.28 0 bottom
T5  WBA0805D801PT-HF  [L4_2012_T]  37.72 62.23 90 bottom
T6  WBA3416L600T-D-HF  [L4_3216_T]  37.72 65.28 0 bottom
T7  WBA0805D801PT-HF  [L4_2012_T]  42.16 62.23 90 bottom
T8  WBA3416L600T-D-HF  [L4_3216_T]  42.16 65.28 0 bottom
U1  ASP9135ZC-R  [SOT23_6]  12.9 63.88 90 top
U2  ASP9135ZC-R  [SOT23_6]  30.1 63.88 90 top
U3  ASP9135ZC-R  [SOT23_6]  24.26 63.88 90 top
U4  ASP9135ZC-R  [SOT23_6]  18.41 63.88 90 top
U5  NS4110B  [SOP-8-EP-2R5X3R4]  13.21 33.65 0 top
U6  NS4110B  [SOP-8-EP-2R5X3R4]  13.21 48 180 top
U7  MT9700  [SOT23-5]  75.56 82.41 180 bottom
U8  CH334F  [QFN24]  91.9 61.41 90 top
U9  MT9700  [SOT23-5]  111.71 48.89 90 top
U10  GM8775C  [QFN45-0R50-7R10X7R10EP5R40X5R40]  25.4 26.16 90 top
U11  74LVC1G125GW  [SOT-353]  7.12 75.67 180 top
U12  74LVC1G125GW  [SOT-353]  2.93 75.67 180 top
U13  MT9700  [SOT23-5]  13.21 20.32 90 top
U14  MT9700  [SOT23-5]  13.21 24 90 top
U15  BM8563EMA  [MSOP-8]  111.58 62.09 90 bottom
U16  BL-M8189FS6  [AP6212]  108.66 61.41 270 top
U17  XL9535  [TSSOP24-0R65-7R80X4R40]  25.4 41.4 180 top
U18  NC  [SOP8]  123.19 27.18 90 bottom
U19  NC  [SOP8]  123.19 37.97 90 bottom
U21  74LVC1T45FZ4-7  [X2-DFN1410-6]  18.41 44.96 0 top
U22  74LVC1T45FZ4-7  [X2-DFN1410-6]  18.41 49.91 0 top
U23  SIT3232EESE  [SOIC16]  95.02 38.99 90 top
U24  SIT3088EESA  [SOP8]  104.9 13.08 90 bottom
U25  SIT3232EESE  [SOIC16]  108.66 38.99 90 top
U26  SIT3088EESA  [SOP8]  90.45 13.08 90 bottom
U27  RT9193-18GB  [SOT23-5]  13.21 27.56 90 top
Y1  12MHz  [3225]  91.9 54.23 0 top
Y2  NC  [3225]  18.08 33.73 180 top
Y3  32.768KHz  [3215]  105.74 61.45 90 bottom
Y4  32.768KHz  [3225]  104.73 49.02 0 top

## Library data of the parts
C1 C4 C6 C9-C11 C14 C17 C19 C21 C22 C24 C27 C32 C34 C35 C40 C45-C47 C50 C53-C61 C63-C65 C67 C68 C70-C72 C75-C77 C79-C82 C85 C86 C92 C94 C96 C98 C101 C103 C104 C107 C109 C111 C112 C117 C122-C124 C127 C128 C130 C132 C133 C135-C144 C146-C156 = CAP_NP: signal model: DEFAULT_CAPACITOR_100000pF_2_1
C2 C12 C15 C25 C73 C74 C115 C120 C157-C159 C161 C165 = CAP_NP
C3 C5 C7 C8 C13 C16 C18 C20 C23 C26 C31 C44 C99 C126 = CAP_NP: signal model: DEFAULT_CAPACITOR_2.2e+07pF_2_1
C28-C30 C41-C43 = CAP_NP: signal model: DEFAULT_CAPACITOR_4.7e+07pF_2_1
C33 C52 C66 C78 C83 C84 C97 C105 C106 C108 C110 C113 C116 C121 C125 C129 C131 C134 C145 C160 C164 = CAP_NP: signal model: DEFAULT_CAPACITOR_1e+07pF_2_1
C36 = CAP_NP: signal model: DEFAULT_CAPACITOR_270.000000pF_2_1
C37 C38 C48 C49 C62 = CAP_NP: signal model: DEFAULT_CAPACITOR_1000pF_2_1
C39 C51 C89 C90 = CAP_NP: signal model: DEFAULT_CAPACITOR_1e+06pF_2_1
C69 = CAP_NP: signal model: DEFAULT_CAPACITOR_4.7e+06pF_2_1
C87 C88 C91 C93 C100 C102 = CAP_NP: signal model: DEFAULT_CAPACITOR_10000pF_2_1
C95 = CAP_NP: signal model: DEFAULT_CAPACITOR_220000pF_2_1
C114 = CAP_NP: signal model: DEFAULT_CAPACITOR_10.000000pF_2_1
C118 C119 = CAP_NP: signal model: DEFAULT_CAPACITOR_18.000000pF_2_1
C162 = CAP_NP: signal model: DEFAULT_CAPACITOR_22000pF_2_1
CN1 = WIFI_ANT
D1-D42 D44 D48-D53 D55-D65 D67-D76 = DIODE BI-DIR TRIG
D43 = BAT54C
D45 D46 D54 D66 = DIODE_SCHTKY
D47 = DIODE
F1 = FUSE
J1 = DC-044A-20A
J2 J8 J14 J33 J34 J37 J38 = 1X4PIN_SH
J3 = RK3562-HH200
J4 J6 J11 J23 J25 = 1X2PIN
J5 = PJ-393
J7 = TF_Card
J9 = USB30_AF
J10 = RC01835
J12 J13 = USB Conn.-Fem-TypeA-TH-RA
J15 = 1X3PIN
J16 J32 J35 J36 = 1X4PIN
J17 = 2X15PIN
J18 = FPC-30P
J19 J21 J22 J31 = 1X6PIN_SH
J20 = 2X3PIN
J24 J28-J30 = FPC-24P
J26 = 1X8PIN_SH
J27 = 1X8PIN
L1 L3-L5 = IND: signal model: DEFAULT_INDUCTOR_3300nH_2_1
L2 L6-L17 = BEAD
LED1 LED2 = LED
Q1 = MOSFET_P
Q2 = NPN
R1 R5 R6 = RES: signal model: DEFAULT_RESISTOR_115000OHM_2_1
R2 R28 R40 R58 R76 R77 R80 R82 R111 R121 R130 R131 R136 R138 R151 R164 R173 R188 = RES: signal model: DEFAULT_RESISTOR_10000OHM_2_1
R3 R10 R15 R25 R39 R56 R67 R137 R179 = RES: signal model: DEFAULT_RESISTOR_1000.000000OHM_2_1
R4 R9 R11 R22 R24 R35 R37 = RES: signal model: DEFAULT_RESISTOR_20000OHM_2_1
R7 = RES: signal model: DEFAULT_RESISTOR_27000OHM_2_1
R8 = RES: signal model: DEFAULT_RESISTOR_180000OHM_2_1
R12 = RES: signal model: DEFAULT_RESISTOR_5100OHM_2_1
R13 R73 R109 R112 R119 R122 = RES: signal model: DEFAULT_RESISTOR_4700OHM_2_1
R14 R26 R29 R31 R61-R63 = RES: signal model: DEFAULT_RESISTOR_100000OHM_2_1
R16 R50 = RES: signal model: DEFAULT_RESISTOR_510.000000OHM_2_1
R17 = RES: signal model: DEFAULT_RESISTOR_30000OHM_2_1
R18 R69-R72 R98 R103 R108 R139-R149 = RES: signal model: DEFAULT_RESISTOR_100.000000OHM_2_1
R19 R23 R27 R30 R33 R34 R36 R38 R41 R42 R49 R51 R60 R78 R79 R81 R84 R85 R132 R150 R155 R156 R158 R165-R170 R172 R182 R184 R186 = RES: signal model: DEFAULT_RESISTOR_0.001OHM_2_1
R20 R174 R175 R189-R192 = RES: signal model: DEFAULT_RESISTOR_2200OHM_2_1
R21 R32 R74 R75 R83 R113-R118 R123-R129 R133 R163 R176-R178 R183 R185 R187 R193 R213-R216 R237-R261 = RES
R43-R48 R135 R152-R154 R157 R159-R162 = RES: signal model: DEFAULT_RESISTOR_22.000000OHM_2_1
R52-R55 = RES: signal model: DEFAULT_RESISTOR_2.200000OHM_2_1
R57 R68 R180 R181 = RES: signal model: DEFAULT_RESISTOR_3400OHM_2_1
R59 = RES: signal model: DEFAULT_RESISTOR_15000OHM_2_1
R64 R65 = RES: signal model: RES_R0402_DISCRETE_2.2R_2.2R
R66 = RES: signal model: DEFAULT_RESISTOR_2700OHM_2_1
R86 R89 R90 R93 R94 R97 R99 R102 R104 R107 = RES: signal model: RES_R0201_DISCRETE_0R_0R
R87 R88 R91 R92 R95 R96 R100 R101 R105 R106 = RES: signal model: RES_R0201_DISCRETE_NC_NC
R110 R120 = RES: signal model: DEFAULT_RESISTOR_120.000000OHM_2_1
R134 = RES: signal model: DEFAULT_RESISTOR_10.000000OHM_2_1
R171 = RES: signal model: DEFAULT_RESISTOR_49900OHM_2_1
SS1-SS4 = SPACER
SW1 = SW_PB_ESW
T1 T3 T5 T7 = IND-4P: signal model: IND-4P_L4_2012_T_WBA0805D801PT-_WBA0805D801PT-HF
T2 T4 T6 T8 = IND-4P
U1-U4 = TP6327GS6
U5 U6 = NS4110B
U7 U9 U13 U14 = MT9700
U8 = FE1.1s-BQFN24B
U10 = GM8775C
U11 U12 = 74LVC1G125
U15 = HYM8563S
U16 = AP6212
U17 = XL9535
U18 U19 = TJA1057GT3_8P
U21 U22 = 74LVC1T45
U23 U25 = MAX3232CSE
U24 U26 = SIT3088E-8P
U27 = RT9193-XXGB
Y1 = CRYSTAL_4P
Y2 Y4 = Oscillator_4P
Y3 = CRYSTAL_2P

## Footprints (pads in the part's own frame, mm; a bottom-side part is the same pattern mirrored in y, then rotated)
3215
  rect 1.4x1.2 smd: 1(-1.001,0) 2(1.001,0)
3225
  rect 1.3x1 smd: 1(-1.15,-0.75) 2(1.15,-0.75) 3(1.15,0.75) 4(-1.15,0.75)
AP6212
  rect 1.5x0.6 smd: 1(-6,4.5) 2(-6,3.6) 3(-6,2.7) 4(-6,1.8) 5(-6,0.9) 6(-6,0) 7(-6,-0.9) 8(-6,-1.8) 9(-6,-2.7) 10(-6,-3.6) 11(-6,-4.5) 23(6,-4.5) 24(6,-3.6) 25(6,-2.7) 26(6,-1.8) 27(6,-0.9) 28(6,0) 29(6,0.9) 30(6,1.8) 31(6,2.7) 32(6,3.6) 33(6,4.5)
  rect 0.6x1.5 smd: 12(-4.5,-6) 13(-3.6,-6) 14(-2.7,-6) 15(-1.8,-6) 16(-0.9,-6) 17(0,-6) 18(0.9,-6) 19(1.8,-6) 20(2.7,-6) 21(3.6,-6) 22(4.5,-6) 34(4.5,6) 35(3.6,6) 36(2.7,6) 37(1.8,6) 38(0.9,6) 39(0,6) 40(-0.9,6) 41(-1.8,6) 42(-2.7,6) 43(-3.6,6) 44(-4.5,6)
  round 0.6 smd: 45(-2.7,3.6) 46(-0.9,3.6) 47(0.9,3.6)
AV7_6X14R50_TM
  round 1.2 hole 1.2 unplated: (0,3.5) (0,-3.5)
  oval 1.2x2 hole 0.75x1.5: 1(-2.3,3.2) 2(-2.3,0.1) 3(-2.3,-2.7) 4(2.3,-3.1) 6(2.3,2) 7(2.3,-0.8) 8(-2.3,-5)
C0402
  rect 0.599x0.599 smd: 1(-0.5,0) 2(0.5,0)
C0603
  rect 0.8x0.8 smd: 1(-0.8,0) 2(0.8,0)
C0805
  rect 1.16x1.47 smd: 1(-0.89,0) 2(0.89,0)
C1206
  rect 1.2x1.9 smd: 1(-1.6,0) 2(1.6,0)
DC_IN_TH_3P_10R1X11R6
  round 1.999 hole 1.999 unplated: (-1.699,-1.25)
  oval 2.4x1.001 hole 1.801x0.399: 1(-2.751,-4.9) 5(-2.751,4.9)
  oval 2.601x1.1 hole 1.699x0.5: 2(4.501,-1.25) 3(4.501,4.049) 4(4.501,-4.45)
ES0402
  rect 0.599x0.599 smd: 1(-0.5,0) 2(0.5,0)
F1812
  rect 1.78x3.3 smd: 1(-2.305,0) 2(2.305,0)
FPC-30P-0P5
  rect 0.3x1.3 smd: 1(-7.25,1.35) 2(-6.75,1.35) 3(-6.25,1.35) 4(-5.75,1.35) 5(-5.25,1.35) 6(-4.75,1.35) 7(-4.25,1.35) 8(-3.75,1.35) 9(-3.25,1.35) 10(-2.75,1.35) 11(-2.25,1.35) 12(-1.75,1.35) 13(-1.25,1.35) 14(-0.75,1.35) 15(-0.25,1.35) 16(0.25,1.35) 17(0.75,1.35) 18(1.25,1.35) 19(1.75,1.35) 20(2.25,1.35) 21(2.75,1.35) 22(3.25,1.35) 23(3.75,1.35) 24(4.25,1.35) 25(4.75,1.35) 26(5.25,1.35) 27(5.75,1.35) 28(6.25,1.35) 29(6.75,1.35) 30(7.25,1.35)
  rect 1.6x2 smd: 31(9.4,-1.35) 32(-9.4,-1.35)
FPC_24P_0P5
  rect 0.3x1.3 smd: 1(-5.75,-1.351) 2(-5.25,-1.351) 3(-4.75,-1.351) 4(-4.25,-1.351) 5(-3.75,-1.351) 6(-3.25,-1.351) 7(-2.75,-1.351) 8(-2.25,-1.351) 9(-1.75,-1.351) 10(-1.25,-1.351) 11(-0.75,-1.351) 12(-0.25,-1.351) 13(0.25,-1.351) 14(0.75,-1.351) 15(1.25,-1.351) 16(1.75,-1.351) 17(2.25,-1.351) 18(2.75,-1.351) 19(3.25,-1.351) 20(3.75,-1.351) 21(4.25,-1.351) 22(4.75,-1.351) 23(5.25,-1.351) 24(5.75,-1.351)
  rect 1.6x2 smd: 25(7.45,1.351) 26(-7.45,1.351)
GH1P25_TH_2P
  rect 0.9x0.9 hole 0.5: 1(-0.625,0)
  round 0.9 hole 0.5: 2(0.625,0)
HC-XH-4AWT
  rect 1.3x4.5 smd: 1(-3.75,0) 2(-1.25,0) 3(1.25,0) 4(3.75,0)
  rect 1.8x3.9 smd: 5(-6.95,-6.8) 6(6.95,-6.8)
HDR1X2-2R54-TM-VM
  rect 1.6x1.6 hole 1: 1(-1.27,0)
  round 1.6 hole 1: 2(1.27,0)
HDR1X3-2R54-TM-VM
  rect 1.6x1.6 hole 1: 1(-2.54,0)
  round 1.6 hole 1: 2(0,0) 3(2.54,0)
HDR1X15-2-TM-RM
  round 1.4 hole 0.8: 1(-14,-1) 2(-14,1) 3(-12,-1) 4(-12,1) 5(-10,-1) 6(-10,1) 7(-8,-1) 8(-8,1) 9(-6,-1) 10(-6,1) 11(-4,-1) 12(-4,1) 13(-2,-1) 14(-2,1) 15(0,-1) 16(0,1) 17(2,-1) 18(2,1) 19(4,-1) 20(4,1) 21(6,-1) 22(6,1) 23(8,-1) 24(8,1) 25(10,-1) 26(10,1) 27(12,-1) 28(12,1) 29(14,-1) 30(14,1)
HDR2X3-2R00-TM-VM
  rect 1.4x1.4 hole 0.8: 1(-2,-1)
  round 1.4 hole 0.8: 2(-2,1) 3(0,-1) 4(0,1) 5(2,-1) 6(2,1)
HH200-0R90-48R1X48R1-B
  rect 0.6x1.6 smd: 1(-22.05,-24.05) 2(-21.15,-24.05) 3(-20.25,-24.05) 4(-19.35,-24.05) 5(-18.45,-24.05) 6(-17.55,-24.05) 7(-16.65,-24.05) 8(-15.75,-24.05) 9(-14.85,-24.05) 10(-13.95,-24.05) 11(-13.05,-24.05) 12(-12.15,-24.05) 13(-11.25,-24.05) 14(-10.35,-24.05) 15(-9.45,-24.05) 16(-8.55,-24.05) 17(-7.65,-24.05) 18(-6.75,-24.05) 19(-5.85,-24.05) 20(-4.95,-24.05) 21(-4.05,-24.05) 22(-3.15,-24.05) 23(-2.25,-24.05) 24(-1.35,-24.05) 25(-0.45,-24.05) 26(0.45,-24.05) 27(1.35,-24.05) 28(2.25,-24.05) 29(3.15,-24.05) 30(4.05,-24.05) 31(4.95,-24.05) 32(5.85,-24.05) 33(6.75,-24.05) 34(7.65,-24.05) 35(8.55,-24.05) 36(9.45,-24.05) 37(10.35,-24.05) 38(11.25,-24.05) 39(12.15,-24.05) 40(13.05,-24.05) 41(13.95,-24.05) 42(14.85,-24.05) 43(15.75,-24.05) 44(16.65,-24.05) 45(17.55,-24.05) 46(18.45,-24.05) 47(19.35,-24.05) 48(20.25,-24.05) 49(21.15,-24.05) 50(22.05,-24.05) 101(22.05,24.05) 102(21.15,24.05) 103(20.25,24.05) 104(19.35,24.05) 105(18.45,24.05) 106(17.55,24.05) 107(16.65,24.05) 108(15.75,24.05) 109(14.85,24.05) 110(13.95,24.05) 111(13.05,24.05) 112(12.15,24.05) 113(11.25,24.05) 114(10.35,24.05) 115(9.45,24.05) 116(8.55,24.05) 117(7.65,24.05) 118(6.75,24.05) 119(5.85,24.05) 120(4.95,24.05) 121(4.05,24.05) 122(3.15,24.05) 123(2.25,24.05) 124(1.35,24.05) 125(0.45,24.05) 126(-0.45,24.05) 127(-1.35,24.05) 128(-2.25,24.05) 129(-3.15,24.05) 130(-4.05,24.05) 131(-4.95,24.05) 132(-5.85,24.05) 133(-6.75,24.05) 134(-7.65,24.05) 135(-8.55,24.05) 136(-9.45,24.05) 137(-10.35,24.05) 138(-11.25,24.05) 139(-12.15,24.05) 140(-13.05,24.05) 141(-13.95,24.05) 142(-14.85,24.05) 143(-15.75,24.05) 144(-16.65,24.05) 145(-17.55,24.05) 146(-18.45,24.05) 147(-19.35,24.05) 148(-20.25,24.05) 149(-21.15,24.05) 150(-22.05,24.05)
  rect 1.6x0.6 smd: 51(24.05,-22.05) 52(24.05,-21.15) 53(24.05,-20.25) 54(24.05,-19.35) 55(24.05,-18.45) 56(24.05,-17.55) 57(24.05,-16.65) 58(24.05,-15.75) 59(24.05,-14.85) 60(24.05,-13.95) 61(24.05,-13.05) 62(24.05,-12.15) 63(24.05,-11.25) 64(24.05,-10.35) 65(24.05,-9.45) 66(24.05,-8.55) 67(24.05,-7.65) 68(24.05,-6.75) 69(24.05,-5.85) 70(24.05,-4.95) 71(24.05,-4.05) 72(24.05,-3.15) 73(24.05,-2.25) 74(24.05,-1.35) 75(24.05,-0.45) 76(24.05,0.45) 77(24.05,1.35) 78(24.05,2.25) 79(24.05,3.15) 80(24.05,4.05) 81(24.05,4.95) 82(24.05,5.85) 83(24.05,6.75) 84(24.05,7.65) 85(24.05,8.55) 86(24.05,9.45) 87(24.05,10.35) 88(24.05,11.25) 89(24.05,12.15) 90(24.05,13.05) 91(24.05,13.95) 92(24.05,14.85) 93(24.05,15.75) 94(24.05,16.65) 95(24.05,17.55) 96(24.05,18.45) 97(24.05,19.35) 98(24.05,20.25) 99(24.05,21.15) 100(24.05,22.05) 151(-24.05,22.05) 152(-24.05,21.15) 153(-24.05,20.25) 154(-24.05,19.35) 155(-24.05,18.45) 156(-24.05,17.55) 157(-24.05,16.65) 158(-24.05,15.75) 159(-24.05,14.85) 160(-24.05,13.95) 161(-24.05,13.05) 162(-24.05,12.15) 163(-24.05,11.25) 164(-24.05,10.35) 165(-24.05,9.45) 166(-24.05,8.55) 167(-24.05,7.65) 168(-24.05,6.75) 169(-24.05,5.85) 170(-24.05,4.95) 171(-24.05,4.05) 172(-24.05,3.15) 173(-24.05,2.25) 174(-24.05,1.35) 175(-24.05,0.45) 176(-24.05,-0.45) 177(-24.05,-1.35) 178(-24.05,-2.25) 179(-24.05,-3.15) 180(-24.05,-4.05) 181(-24.05,-4.95) 182(-24.05,-5.85) 183(-24.05,-6.75) 184(-24.05,-7.65) 185(-24.05,-8.55) 186(-24.05,-9.45) 187(-24.05,-10.35) 188(-24.05,-11.25) 189(-24.05,-12.15) 190(-24.05,-13.05) 191(-24.05,-13.95) 192(-24.05,-14.85) 193(-24.05,-15.75) 194(-24.05,-16.65) 195(-24.05,-17.55) 196(-24.05,-18.45) 197(-24.05,-19.35) 198(-24.05,-20.25) 199(-24.05,-21.15) 200(-24.05,-22.05)
L4_2012_T
  rect 0.675x0.475 smd: 1(-0.963,0.463) 2(0.963,0.463) 3(0.963,-0.463) 4(-0.963,-0.463)
L4_3216_T
  rect 0.7x0.6 smd: 1(-1.5,0.55) 2(1.5,0.55) 3(1.5,-0.55) 4(-1.5,-0.55)
L0603
  rect 0.8x0.8 smd: 1(-0.8,0) 2(0.8,0)
L4520
  rect 1.4x2.3 smd: 1(-1.8,0) 2(1.8,0)
LED_HS_0602_UR
  rect 0.77x0.6 smd: 1(-0.815,0) 2(0.815,0)
MSOP-8
  rect 0.3x1 smd: 1(-0.975,-2.2) 2(-0.325,-2.2) 3(0.325,-2.2) 4(0.975,-2.2) 5(0.975,2.2) 6(0.325,2.2) 7(-0.325,2.2) 8(-0.975,2.2)
PH2R0-A-1X4
  rect 0.9x3 smd: 1(-5,-3.8) 2(-3,-3.8) 3(-1,-3.8) 4(1,-3.8)
  rect 0.8x3 smd: 5(3.25,2.55) 6(-7.25,2.55)
PH2R0-A-1X6
  rect 0.9x3 smd: 1(-5,-3.8) 2(-3,-3.8) 3(-1,-3.8) 4(1,-3.8) 5(3,-3.8) 6(5,-3.8)
  rect 0.8x3 smd: 7(7.25,2.55) 8(-7.25,2.55)
PH2R0-A-1X8
  rect 0.9x3 smd: 1(-7,-3.8) 2(-5,-3.8) 3(-3,-3.8) 4(-1,-3.8) 5(1,-3.8) 6(3,-3.8) 7(5,-3.8) 8(7,-3.8)
  rect 0.8x3 smd: 9(9.25,2.55) 10(-9.25,2.55)
PH-1X2-2P0_L
  rect 1.1x1.1 hole 0.7: 1(-1,0)
  round 1.1 hole 0.7: 2(1,0)
PH-1X4-2P0
  rect 1.1x1.1 hole 0.7: 1(-3,0)
  round 1.1 hole 0.7: 2(-1,0) 3(1,0) 4(3,0)
PH-1X8-2P0
  rect 1.1x1.1 hole 0.7: 1(-7,0)
  round 1.1 hole 0.7: 2(-5,0) 3(-3,0) 4(-1,0) 5(1,0) 6(3,0) 7(5,0) 8(7,0)
PTH_M3
  round 6.2 hole 3.1: 1(0,0)
QFN24
  rect 1x0.3 smd: 1(-2.1,1.25) 2(-2.1,0.75) 3(-2.1,0.25) 4(-2.1,-0.25) 5(-2.1,-0.75) 6(-2.1,-1.25) 13(2.1,-1.25) 14(2.1,-0.75) 15(2.1,-0.25) 16(2.1,0.25) 17(2.1,0.75) 18(2.1,1.25)
  rect 0.3x1 smd: 7(-1.25,-2.1) 8(-0.75,-2.1) 9(-0.25,-2.1) 10(0.25,-2.1) 11(0.75,-2.1) 12(1.25,-2.1) 19(1.25,2.1) 20(0.75,2.1) 21(0.25,2.1) 22(-0.25,2.1) 23(-0.75,2.1) 24(-1.25,2.1)
  rect 2x2 smd: 25(0,0)
QFN45-0R50-7R10X7R10EP5R40X5R40
  rect 0.2x0.8 smd: 1(-2.75,-3.45) 2(-2.25,-3.45) 3(-1.75,-3.45) 4(-1.25,-3.45) 5(-0.75,-3.45) 6(-0.25,-3.45) 7(0.25,-3.45) 8(0.75,-3.45) 9(1.25,-3.45) 10(1.75,-3.45) 11(2.25,-3.45) 12(2.75,-3.45) 25(2.75,3.45) 26(2.25,3.45) 27(1.75,3.45) 28(1.25,3.45) 29(0.75,3.45) 30(0.25,3.45) 31(-0.25,3.45) 32(-0.75,3.45) 33(-1.25,3.45) 34(-1.75,3.45) 35(-2.25,3.45) 36(-2.75,3.45)
  rect 0.8x0.2 smd: 13(3.45,-2.75) 14(3.45,-2.25) 15(3.45,-1.75) 16(3.45,-1.25) 17(3.45,-0.75) 18(3.45,-0.25) 19(3.45,0.25) 20(3.45,0.75) 21(3.45,1.25) 22(3.45,1.75) 23(3.45,2.25) 24(3.45,2.75) 37(-3.45,2.75) 38(-3.45,2.25) 39(-3.45,1.75) 40(-3.45,1.25) 41(-3.45,0.75) 42(-3.45,0.25) 43(-3.45,-0.25) 44(-3.45,-0.75) 45(-3.45,-1.25) 46(-3.45,-1.75) 47(-3.45,-2.25) 48(-3.45,-2.75)
  rect 5x5 smd: 49(0,0)
R0201
  rect 0.35x0.35 smd: 1(-0.275,0) 2(0.275,0)
R0402
  rect 0.599x0.599 smd: 1(-0.5,0) 2(0.5,0)
R0603
  rect 0.8x0.8 smd: 1(-0.8,0) 2(0.8,0)
R0805
  rect 1.016x1.143 smd: 1(-1.016,0) 2(1.016,0)
RJ8-15R2X16R2-TM-LED
  round 1.2 hole 0.8: 1(-3.57,-6.5) 2(-2.55,-7.6) 3(-1.53,-6.5) 4(-0.51,-7.6) 5(0.51,-6.5) 6(1.53,-7.6) 7(2.55,-6.5) 8(3.57,-7.6) 9(-7.06,-5.4) 10(-4.77,-5.4) 11(4.77,-5.4) 12(7.06,-5.4)
  oval 1.6x3 hole 1x2.4: 13(-8,0) 14(8,0)
SOD323_T
  rect 0.8x0.8 smd: 1(-1.175,0) 2(1.175,0)
SOD523
  rect 0.6x0.7 smd: 1(-0.71,0) 2(0.71,0)
SOD-123
  rect 1.2x1.4 smd: 1(1.7,0) 2(-1.7,0)
SOIC16
  oval 2.032x0.61 smd: 1(-2.789,4.44) 2(-2.789,3.18) 3(-2.789,1.9) 4(-2.789,0.64) 5(-2.789,-0.64) 6(-2.789,-1.9) 7(-2.789,-3.18) 8(-2.789,-4.44) 9(2.789,-4.44) 10(2.789,-3.18) 11(2.789,-1.9) 12(2.789,-0.64) 13(2.789,0.64) 14(2.789,1.9) 15(2.789,3.18) 16(2.789,4.44)
SOP8
  oval 0.6x1.8 smd: 1(-1.905,-2.5) 2(-0.635,-2.5) 3(0.635,-2.5) 4(1.905,-2.5) 5(1.905,2.5) 6(0.635,2.5) 7(-0.635,2.5) 8(-1.905,2.5)
SOP-8-EP-2R5X3R4
  oval 0.4x1.4 smd: 1(-1.905,-2.6) 2(-0.635,-2.6) 3(0.635,-2.6) 4(1.905,-2.6) 5(1.905,2.6) 6(0.635,2.6) 7(-0.635,2.6) 8(-1.905,2.6)
  rect 3.3x2.4 smd: 9(0,0)
SOT23
  rect 0.914x0.914 smd: 1(-0.953,-0.991) 2(0.953,-0.991)
  rect 0.914x1.27 smd: 3(0,1.041)
SOT23-5
  rect 0.599x1.199 smd: 1(-0.95,-1.25) 2(0,-1.25) 3(0.95,-1.25) 4(0.95,1.25) 5(-0.95,1.25)
SOT23_6
  rect 0.7x0.9 smd: 1(-0.95,-1.2) 2(0,-1.2) 3(0.95,-1.2) 4(0.95,1.2) 5(0,1.2) 6(-0.95,1.2)
SOT-353
  rect 0.406x1.194 smd: 1(-0.65,-0.9) 2(0,-0.9) 3(0.65,-0.9) 4(0.65,0.9) 5(-0.65,0.9)
SW4-4R20X3R25-SM
  rect 1.2x0.65 smd: 1(-2.15,1.075) 2(2.15,1.075) 3(2.15,-1.075) 4(-2.15,-1.075)
TFCARD
  round 1 hole 1 unplated: (-4,0) (4,0)
  rect 0.7x1.6 smd: 1(3.2,10.5) 2(2.1,10.5) 3(1,10.5) 4(-0.1,10.5) 5(-1.2,10.5) 6(-2.3,10.5) 7(-3.4,10.5) 8(-4.5,10.5) 9(-5.6,10.5)
  rect 1.2x1.778 smd: 10(-6.8,10)
  rect 1.524x2.413 smd: 11(-6.8,0.4) 12(8.7,0.4)
  rect 1.778x1.778 smd: 13(7.8,10)
TSSOP24-0R65-7R80X4R40
  rect 1.1x0.3 smd: 1(-2.95,3.575) 2(-2.95,2.925) 3(-2.95,2.275) 4(-2.95,1.625) 5(-2.95,0.975) 6(-2.95,0.325) 7(-2.95,-0.325) 8(-2.95,-0.975) 9(-2.95,-1.625) 10(-2.95,-2.275) 11(-2.95,-2.925) 12(-2.95,-3.575) 13(2.95,-3.575) 14(2.95,-2.925) 15(2.95,-2.275) 16(2.95,-1.625) 17(2.95,-0.975) 18(2.95,-0.325) 19(2.95,0.325) 20(2.95,0.975) 21(2.95,1.625) 22(2.95,2.275) 23(2.95,2.925) 24(2.95,3.575)
UFL-3
  rect 1.05x1.05 smd: 1(0,-1.5)
  rect 1.05x2.2 smd: 2(-1.5,0) 3(1.5,0)
unnamed
  round 1.016 smd: 1(0,0)
USB9-A-16R5X14R45-TM
  round 1.1 hole 0.7: 1(-3.5,2) 2(-1,2) 3(1,2) 4(3.5,2) 5(4,3.5) 6(2,3.5) 7(0,3.5) 8(-2,3.5) 9(-4,3.5)
  round 2.9 hole 2.3: 10(-6.57,0) 11(6.57,0)
USB-A-SM
  rect 1.6x1.6 hole 0.9: 1(-3.5,0)
  round 1.6 hole 0.9: 2(-1,0) 3(1,0) 4(3.5,0)
  round 3.3 hole 2.3: 5(-6.57,-2.714) 6(6.57,-2.714)
X2-DFN1410-6
  rect 0.2x0.5 smd: 1(-0.5,-0.375) 2(0,-0.375) 3(0.5,-0.375) 4(0.5,0.375) 5(0,0.375) 6(-0.5,0.375)
ZH1P5MM_TH_2P
  round 1.05 hole 0.65: 1(-0.75,0) 2(0.75,0)

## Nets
12V: C5.1 C6.1 C7.1 C8.1 C9.1 C18.1 C19.1 C20.1 C21.1 C26.1 C27.1 F1.2 R8.2 R19.1 R30.1 R79.1 R133.1 U1.3(VIN) U2.3(VIN) U3.3(VIN) U4.3(VIN)
12V_IN: F1.1 J1.4 J2.3 J2.4
